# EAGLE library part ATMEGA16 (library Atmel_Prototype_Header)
8-bit AVR Microcontroller with 16K Bytes In-System Programmable Flash
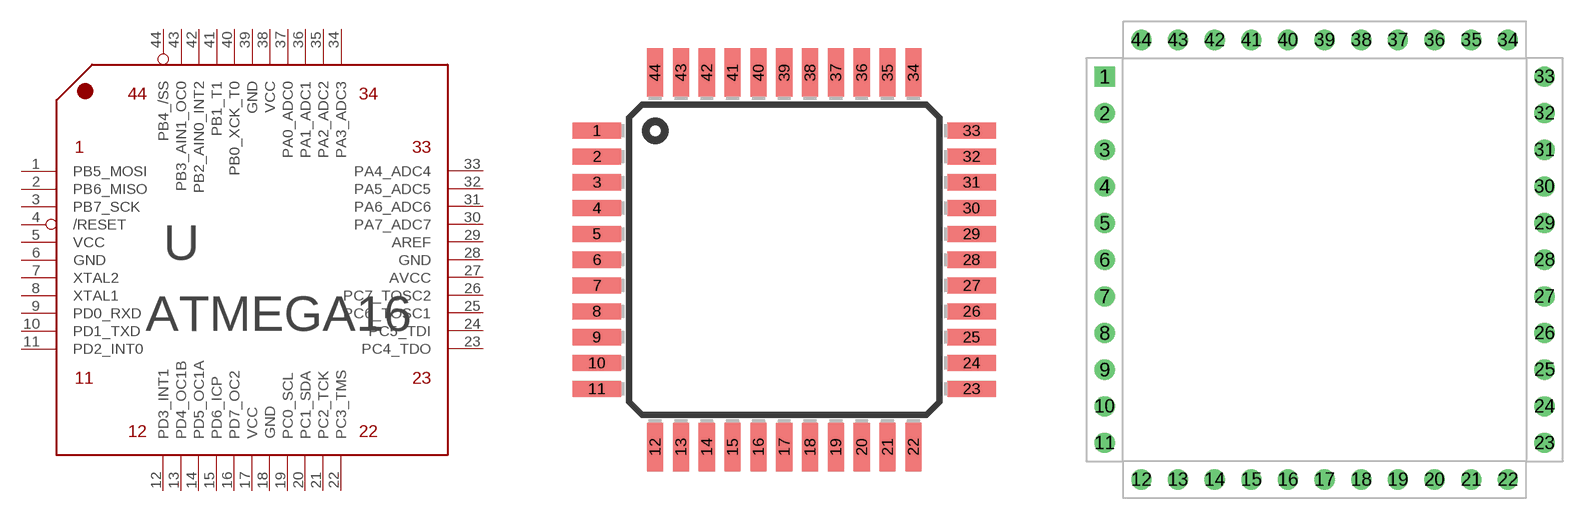
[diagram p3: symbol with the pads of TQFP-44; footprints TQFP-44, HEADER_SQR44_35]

Designator prefix U

## ATMEGA16-16AI  [TQFP-44]
1  PB5_MOSI
2  PB6_MISO
3  PB7_SCK
4  /RESET
5  VCC
6  GND
7  XTAL2
8  XTAL1
9  PD0_RXD
10  PD1_TXD
11  PD2_INT0
12  PD3_INT1
13  PD4_OC1B
14  PD5_OC1A
15  PD6_ICP
16  PD7_OC2
17  VCC
18  GND
19  PC0_SCL
20  PC1_SDA
21  PC2_TCK
22  PC3_TMS
23  PC4_TDO
24  PC5_TDI
25  PC6_TOSC1
26  PC7_TOSC2
27  AVCC
28  GND
29  AREF
30  PA7_ADC7
31  PA6_ADC6
32  PA5_ADC5
33  PA4_ADC4
34  PA3_ADC3
35  PA2_ADC2
36  PA1_ADC1
37  PA0_ADC0
38  VCC
39  GND
40  PB0_XCK_T0
41  PB1_T1
42  PB2_AIN0_INT2
43  PB3_AIN1_OC0
44  PB4_/SS

## ATMEGA16_SINGLE44_35  [HEADER_SQR44_35]
Pads as for TQFP-44

## ATMEGA16_SINGLE44_43  [HEADER_SQR44_43]
Pads as for TQFP-44

## ATMEGA16_DUAL44_43  [HEADER_DUALSQR44_43]
Pads as for TQFP-44

## ATMEGA16_DUAL44_35  [HEADER_DUALSQR44_35]
Pads as for TQFP-44

## ATMEGA16_PLCC_SOCKET  [PLCC-S44]
Pads as for TQFP-44

## Footprint TQFP-44 (pad centres in mm)
smd 1.5 x 0.5: 1 -5.8,4; 2 -5.8,3.2; 3 -5.8,2.4; 4 -5.8,1.6; 5 -5.8,0.8; 6 -5.8,0; 7 -5.8,-0.8; 8 -5.8,-1.6; 9 -5.8,-2.4; 10 -5.8,-3.2; 11 -5.8,-4; 23 5.8,-4; 24 5.8,-3.2; 25 5.8,-2.4; 26 5.8,-1.6; 27 5.8,-0.8; 28 5.8,0; 29 5.8,0.8; 30 5.8,1.6; 31 5.8,2.4; 32 5.8,3.2; 33 5.8,4
smd 0.5 x 1.5: 12 -4,-5.8; 13 -3.2,-5.8; 14 -2.4,-5.8; 15 -1.6,-5.8; 16 -0.8,-5.8; 17 0,-5.8; 18 0.8,-5.8; 19 1.6,-5.8; 20 2.4,-5.8; 21 3.2,-5.8; 22 4,-5.8; 34 4,5.8; 35 3.2,5.8; 36 2.4,5.8; 37 1.6,5.8; 38 0.8,5.8; 39 0,5.8; 40 -0.8,5.8; 41 -1.6,5.8; 42 -2.4,5.8; 43 -3.2,5.8; 44 -4,5.8

## Footprint HEADER_SQR44_35 (pad centres in mm)
drill 0.889 square: 1 -15.24,12.7
drill 0.889 round: 2 -15.24,10.16; 3 -15.24,7.62; 4 -15.24,5.08; 5 -15.24,2.54; 6 -15.24,0; 7 -15.24,-2.54; 8 -15.24,-5.08; 9 -15.24,-7.62; 10 -15.24,-10.16; 11 -15.24,-12.7; 12 -12.7,-15.24; 13 -10.16,-15.24; 14 -7.62,-15.24; 15 -5.08,-15.24; 16 -2.54,-15.24; 17 0,-15.24; 18 2.54,-15.24; 19 5.08,-15.24; 20 7.62,-15.24; 21 10.16,-15.24; 22 12.7,-15.24; 23 15.24,-12.7; 24 15.24,-10.16; 25 15.24,-7.62; 26 15.24,-5.08; 27 15.24,-2.54; 28 15.24,0; 29 15.24,2.54; 30 15.24,5.08; 31 15.24,7.62; 32 15.24,10.16; 33 15.24,12.7; 34 12.7,15.24; 35 10.16,15.24; 36 7.62,15.24; 37 5.08,15.24; 38 2.54,15.24; 39 0,15.24; 40 -2.54,15.24; 41 -5.08,15.24; 42 -7.62,15.24; 43 -10.16,15.24; 44 -12.7,15.24

## Footprint HEADER_SQR44_43 (pad centres in mm)
drill 1.1 square: 1 -15.24,12.7
drill 1.1 round: 2 -15.24,10.16; 3 -15.24,7.62; 4 -15.24,5.08; 5 -15.24,2.54; 6 -15.24,0; 7 -15.24,-2.54; 8 -15.24,-5.08; 9 -15.24,-7.62; 10 -15.24,-10.16; 11 -15.24,-12.7; 12 -12.7,-15.24; 13 -10.16,-15.24; 14 -7.62,-15.24; 15 -5.08,-15.24; 16 -2.54,-15.24; 17 0,-15.24; 18 2.54,-15.24; 19 5.08,-15.24; 20 7.62,-15.24; 21 10.16,-15.24; 22 12.7,-15.24; 23 15.24,-12.7; 24 15.24,-10.16; 25 15.24,-7.62; 26 15.24,-5.08; 27 15.24,-2.54; 28 15.24,0; 29 15.24,2.54; 30 15.24,5.08; 31 15.24,7.62; 32 15.24,10.16; 33 15.24,12.7; 34 12.7,15.24; 35 10.16,15.24; 36 7.62,15.24; 37 5.08,15.24; 38 2.54,15.24; 39 0,15.24; 40 -2.54,15.24; 41 -5.08,15.24; 42 -7.62,15.24; 43 -10.16,15.24; 44 -12.7,15.24

## Footprint HEADER_DUALSQR44_43 (pad centres in mm)
drill 1.1 square: 1 -8.89,6.35
drill 1.1 round: 2 -11.43,3.81; 3 -8.89,3.81; 4 -11.43,1.27; 5 -8.89,1.27; 6 -11.43,-1.27; 7 -8.89,-1.27; 8 -11.43,-3.81; 9 -8.89,-3.81; 10 -11.43,-6.35; 11 -8.89,-6.35; 12 -6.35,-8.89; 13 -3.81,-11.43; 14 -3.81,-8.89; 15 -1.27,-11.43; 16 -1.27,-8.89; 17 1.27,-11.43; 18 1.27,-8.89; 19 3.81,-11.43; 20 3.81,-8.89; 21 6.35,-11.43; 22 6.35,-8.89; 23 8.89,-6.35; 24 11.43,-3.81; 25 8.89,-3.81; 26 11.43,-1.27; 27 8.89,-1.27; 28 11.43,1.27; 29 8.89,1.27; 30 11.43,3.81; 31 8.89,3.81; 32 11.43,6.35; 33 8.89,6.35; 34 6.35,8.89; 35 3.81,11.43; 36 3.81,8.89; 37 1.27,11.43; 38 1.27,8.89; 39 -1.27,11.43; 40 -1.27,8.89; 41 -3.81,11.43; 42 -3.81,8.89; 43 -6.35,11.43; 44 -6.35,8.89
hole 1.1 at -11.43,6.35
hole 1.1 at -6.35,-11.43
hole 1.1 at 11.43,-6.35
hole 1.1 at 6.35,11.43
